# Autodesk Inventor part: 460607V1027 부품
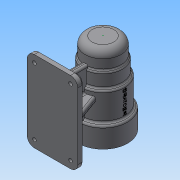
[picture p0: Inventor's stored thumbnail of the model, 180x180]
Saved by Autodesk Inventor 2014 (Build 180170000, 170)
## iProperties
Created: 2016-06
Part Number: 460607V1027 부품
Material: 일반
Document SubType Name: Modeling
Designer: NET
Density: 1 g/cm^3
Appearance: 기본값
Author: NET
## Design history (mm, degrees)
sketch "스케치6"
  geometry: L1 (0, 0)-(25, 0); L2 (25, 0)-(25, -25); L3 (25, -25)-(27, -25); L4 (27, -25)-(27, -45); L5 (27, -45)-(30, -45); L6 (30, -45)-(30, -84); L7 (30, -84)-(34, -84); L8 (34, -84)-(34, -112); L9 (34, -112)-(0, -112); L10 (0, -112)-(0, 0)
  constraints: 20 end point, 8 parallel, 1 horizontal, 1 perpendicular
  dimensions: "d13" = 112 distance between parallel lines of L1 L9; "d14" = 84 distance between parallel lines of L7 L1; "d15" = 45 distance between parallel lines of L1 L5; "d16" = 25 distance between parallel lines of L3 L1; "d17" = 25 distance between parallel lines of L10 L2; "d18" = 27 distance between parallel lines of L10 L4; "d19" = 30 distance between parallel lines of L10 L6; "d20" = 34 distance between parallel lines of L10 L8
revolve "회전1" sketch "스케치6" stored, may be unused: angle "d21" = 90 deg
sketch "스케치7"
  geometry: 1 further point
node "작업 평면1"
sketch "스케치8"
  geometry: L1 (-35, 0)-(35, 0); L2 (35, 0)-(35, -112); L3 (35, -112)-(-35, -112); L4 (-35, -112)-(-35, 0); 2 further points
  constraints: 8 end point, 2 parallel, 1 coincident, 1 horizontal, 1 midpoint, 1 perpendicular
  dimensions: "d23" = 70 distance of L1.start L1.end; "d24" = 112 distance from line of L2.end L1
extrude "돌출5" join sketch "스케치8" distance "d25" = 10; taper "d26" = 0 deg
sketch "스케치9"
  geometry: L1 (-70, 0)-(-60, 0) reference; L2 (-70, -112)-(-60, -112) reference; L3 (-34, -84)-(-34, -112) reference; L4 (-30, -45)-(-30, -84) reference; L5 (-27, -25)-(-27, -45) reference; L6 (-25, 0)-(-25, -25) reference; L7 (-70, -92)-(-12.802, -92); L8 (-70, -20)-(-12.802, -20); L9 (-12.802, -20)-(-12.802, -92); L10 (-70, -20)-(-70, -92); 1 further point
  constraints: 8 end point, 3 parallel, 2 perpendicular
  dimensions: "d29" = 20 distance between parallel lines of L2 L7; "d30" = 20 distance between parallel lines of L1 L8; "d31" = 57.19766 distance between parallel lines of L9 L10; "d32" = 17.19766 distance between parallel lines of L4 L9
extrude "돌출6" join sketch "스케치9" stored distance "d33" = 8; taper "d34" = 0 deg
node "작업 평면2"
sketch "스케치10"
  geometry: 1 further point
fillet "모깎기1" dims "d35" = 10
chamfer "모따기1" distance "d36" = 4; stored, may be unused: second distance "d37" = 2, angle "d38" = 45 deg
sketch "스케치11"
  geometry: L1 (10, 10)-(60, 10) reference; L2 (60, 10)-(66, 10) reference; L3 (4, 10)-(10, 10) reference; L4 (63, 10)-(48.168, 50.749); L5 (7, 10)-(21.832, 50.749); L6 (21.832, 50.749)-(48.168, 50.749); L7 (7, 10)-(63, 10); L8 (35, 50.749)-(35, 10); 1 further point
  constraints: 10 end point, 3 midpoint, 1 collinear
  dimensions: "d42" = 26.3369 distance of L5.end L4.end; "d43" = 43.36455 distance of L5.start L5.end; "d44" = 70 deg angle of L1 L5; "d45" = 20 deg angle of L4 L8; "d46" = 20 deg angle of L5 L8
extrude "돌출7" join sketch "스케치11" stored distance "d47" = 8; taper "d48" = 0 deg
fillet "모깎기2" dims "d49" = 3
fillet "모깎기3" dims "d50" = 3
fillet "모깎기4" dims "d51" = 3
fillet "모깎기5" dims "d52" = 3
fillet "모깎기6" dims "d53" = 10
sketch "스케치12"
  geometry: C1 r 34 at (0, 0) reference; C2 r 21 at (0, 0)
  constraints: 1 centre point, 1 coincident
  dimensions: "d54" = 42 diameter of C2
extrude "돌출8" cut sketch "스케치12" distance "d55" = 15; taper "d56" = 0 deg
sketch "스케치13"
  geometry: C1 r 21 at (0, 0) reference; C2 r 24 at (0, 0)
  constraints: 1 centre point, 1 coincident
  dimensions: "d57" = 48 diameter of C2
extrude "돌출9" cut sketch "스케치13" distance "d58" = 54; taper "d59" = 0 deg
sketch "스케치14"
  geometry: C1 r 24 at (0, 0) reference; C2 r 21 at (0, 0)
  constraints: 1 centre point, 1 coincident
  dimensions: "d60" = 42 diameter of C2
extrude "돌출10" cut sketch "스케치14" distance "d61" = 12; taper "d62" = 0 deg
sketch "스케치15"
  geometry: C1 r 21 at (0, 0) reference; C2 r 17.5 at (0, 0)
  constraints: 1 centre point, 1 coincident
  dimensions: "d63" = 35 diameter of C2
extrude "돌출11" cut sketch "스케치15" distance "d64" = 18; taper "d65" = 0 deg
sketch "스케치16"
  geometry: C1 r 17.5 at (0, 0) reference; C2 r 16 at (0, 0)
  constraints: 1 centre point, 1 coincident
  dimensions: "d66" = 32 diameter of C2
extrude "돌출12" cut sketch "스케치16" distance "d67" = 4; taper "d68" = 0 deg
sketch "스케치17"
  geometry: C1 r 16 at (0, 0) reference; C2 r 10.5 at (0, 0)
  constraints: 1 centre point, 1 coincident
  dimensions: "d69" = 21 diameter of C2
extrude "돌출13" cut sketch "스케치17" distance "d70" = 3; taper "d71" = 0 deg
fillet "모깎기7" dims "d72" = 3
fillet "모깎기8" dims "d73" = 0.3
fillet "모깎기9" dims "d74" = 3
fillet "모깎기10" dims "d75" = 3
chamfer "모따기2" distance "d76" = 1; stored, may be unused: second distance "d77" = 2, angle "d78" = 45 deg
sketch "스케치19" dims "d79" = 52
  geometry: L1 (0, 0)-(0, 26); C1 r 22 at (0, 0) reference; 1 further point
  constraints: 2 coincident, 2 end point, 1 vertical, 1 vertical alignment, 2 other
hole "구멍1" sketch "스케치19" at (0, 26) diameter "d80" = 4; stored, may be unused: countersink angle "d84" = 90 deg, drill point angle "d86" = 118 deg; dims "d81" = 6, "d82" = 4, "d83" = 2, "d85" = 11
feature "스레드1" dims "d87" = 8, "d88" = 0
node "작업 평면3"
sketch "스케치20"
  geometry: L1 (-34, -112)-(34, -112) reference; 2 further points
  constraints: 1 other
  dimensions: "d93" = 48 distance from line of L1 point (0, -64); "d94" = 0 horizontal distance of point (0, -64) point (0, 0)
feature "엠보싱1" sketch "스케치20" dims "d13" = 112, "d14" = 84, "d15" = 45, "d16" = 25, "d17" = 25, "d18" = 27, "d19" = 30, "d20" = 34, "d26" = 0, "d95" = 0.5, "d96" = 0
node "작업 평면4"
hole "구멍2" diameter "d110" = 5; stored, may be unused: countersink angle "d114" = 90 deg, drill point angle "d116" = 118 deg; dims "d108" = 10, "d109" = 10, "d111" = 6, "d112" = 9, "d113" = 4, "d115" = 8
node "솔리드2"
pattern_circular "원형 패턴1" dims angle "d90" = 360 deg
mirror "대칭2"
mirror "대칭3"
